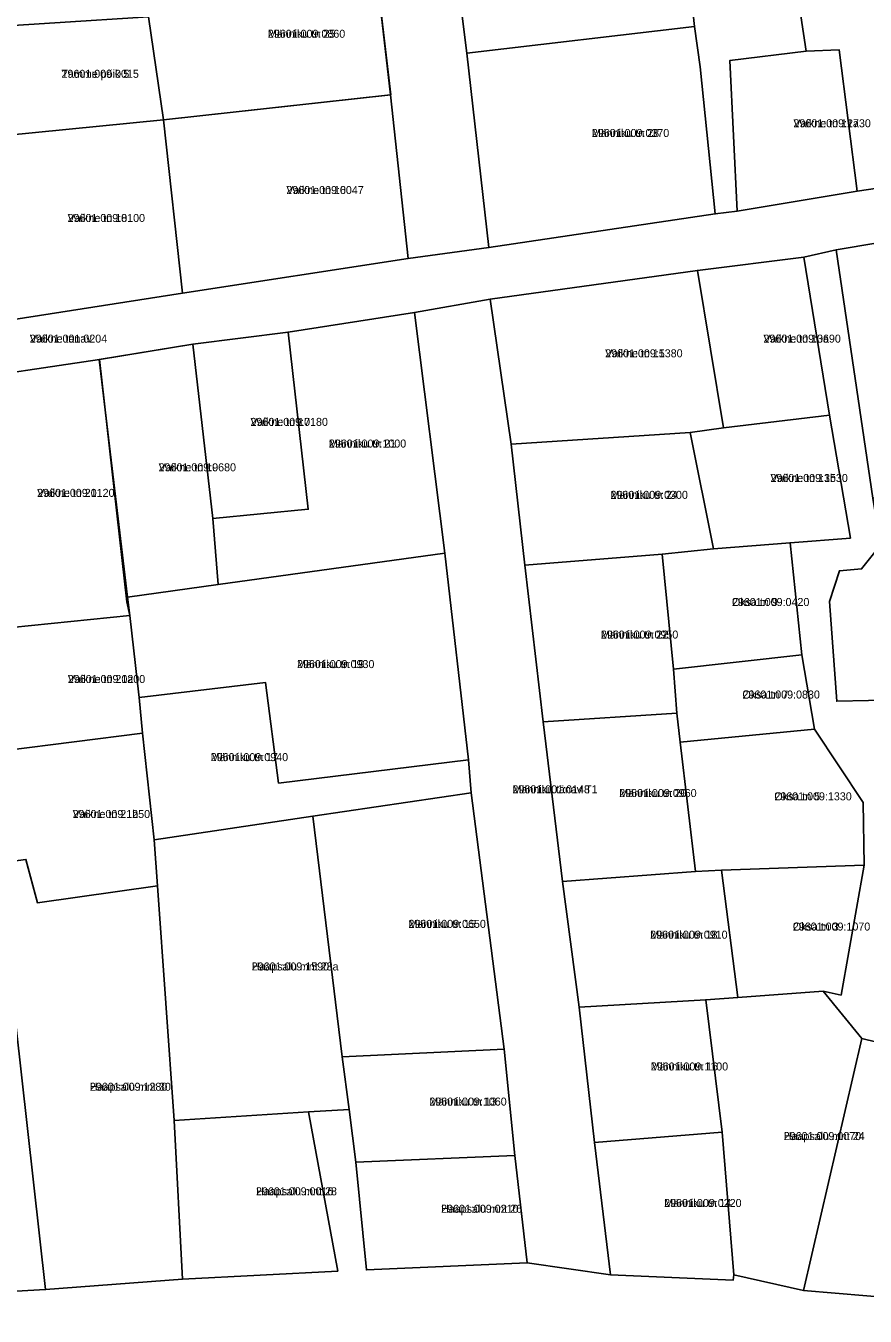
# Model space of a CAD drawing. Extents: x 518839 to 525192, y 6573164 to 6576561.
# Drawn here: x 523208.1 to 523365.3, y 6574453 to 6574694.8 of the extents above; entities that cross this region are included whole.
import ezdxf

# ---------------------------------------------------------------- set-up
doc = ezdxf.new("R2010")
doc.units = 0
for name, color, linetype in [('L_AADRESS', 7, 'Continuous'), ('PIIR', 7, 'Continuous'), ('TUNNUS', 7, 'Continuous')]:
    doc.layers.add(name, color=color, linetype=linetype)

msp = doc.modelspace()

# ---------------------------------------------------------------- linework, layer by layer
at = {"layer": 'PIIR'}
for points in [[(523270.92, 6574729.71), (523267.53, 6574756.92), (523282.17, 6574758.8), (523284.18, 6574742.92), (523288.32, 6574708.6), (523290.68, 6574689.65), (523294.84, 6574653.21), (523279.72, 6574651.19), (523276.41, 6574681.83), (523273.42, 6574707.86)], [(523371.76, 6574716.56), (523372.55, 6574716.47), (523377.4, 6574692.22), (523381.14, 6574666.32), (523363.81, 6574663.75), (523360.45, 6574690.27), (523354.26, 6574689.99), (523350.61, 6574714.52)], [(523341.33, 6574660.04), (523337.24, 6574659.51), (523334.44, 6574687.09), (523333.39, 6574694.64), (523331.45, 6574712.67), (523350.61, 6574714.52), (523354.26, 6574689.99), (523339.99, 6574688.28)], [(523288.32, 6574708.6), (523331.45, 6574712.67), (523333.39, 6574694.64), (523290.68, 6574689.65)], [(523231.04, 6574696.45), (523230.21, 6574703.79), (523273.42, 6574707.86), (523276.47, 6574681.84), (523233.85, 6574677.17)], [(523231.04, 6574696.45), (523233.85, 6574677.17), (523197.86, 6574673.59), (523195.92, 6574694.21)], [(523290.68, 6574689.65), (523333.39, 6574694.64), (523334.44, 6574687.09), (523337.24, 6574659.51), (523294.84, 6574653.21)], [(523339.99, 6574688.28), (523354.26, 6574689.99), (523360.45, 6574690.27), (523363.81, 6574663.75), (523341.33, 6574660.04)], [(523233.85, 6574677.17), (523276.41, 6574681.83), (523279.72, 6574651.19), (523237.4, 6574644.64)], [(523237.4, 6574644.64), (523199.77, 6574638.82), (523196.52, 6574654.74), (523194.48, 6574664.75), (523192.78, 6574673.06), (523197.86, 6574673.59), (523233.85, 6574677.17)], [(523384.07, 6574656.83), (523391.71, 6574615.04), (523392.97, 6574610.47), (523366.8, 6574606.26), (523359.93, 6574652.76)], [(523358.63, 6574621.78), (523338.77, 6574619.44), (523333.92, 6574648.94), (523353.84, 6574651.4)], [(523295.09, 6574643.54), (523333.92, 6574648.94), (523338.77, 6574619.44), (523332.54, 6574618.56), (523299.02, 6574616.36)], [(523286.59, 6574595.96), (523280.89, 6574641.02), (523295.09, 6574643.54), (523299.02, 6574616.36), (523301.6, 6574593.7), (523304.99, 6574564.37), (523308.6, 6574534.46), (523311.75, 6574510.89), (523314.62, 6574485.52), (523317.63, 6574460.76), (523301.99, 6574462.99), (523299.72, 6574483.07), (523297.72, 6574503.04), (523291.5, 6574551.06), (523291.03, 6574557.25)], [(523243.09, 6574602.43), (523260.98, 6574604.17), (523257.22, 6574637.37), (523280.89, 6574641.02), (523286.59, 6574595.96), (523244.08, 6574590.06)], [(523239.37, 6574635.11), (523257.22, 6574637.37), (523260.98, 6574604.17), (523243.09, 6574602.43)], [(523221.81, 6574632.22), (523239.37, 6574635.11), (523243.09, 6574602.43), (523244.08, 6574590.06), (523227.1, 6574587.71)], [(523192.82, 6574624.06), (523193.28, 6574628), (523221.88, 6574632.21), (523227, 6574586.83), (523227.56, 6574584.27), (523201.72, 6574581.64), (523197.9, 6574581.44)], [(523332.54, 6574618.56), (523338.77, 6574619.44), (523358.63, 6574621.78), (523362.58, 6574598.77), (523351.26, 6574597.9), (523336.94, 6574596.79)], [(523299.02, 6574616.36), (523332.54, 6574618.56), (523336.94, 6574596.79), (523327.31, 6574595.75), (523301.6, 6574593.7)], [(523366.8, 6574606.26), (523392.97, 6574610.47), (523387.38, 6574595.16), (523377.83, 6574568.61), (523360.01, 6574568.22), (523358.68, 6574586.91), (523360.51, 6574592.67), (523364.67, 6574593.01), (523367.38, 6574596.44), (523367.82, 6574599.7)], [(523327.31, 6574595.75), (523336.94, 6574596.79), (523351.26, 6574597.9), (523353.46, 6574576.93), (523329.42, 6574574.21)], [(523227.56, 6574584.27), (523227.1, 6574587.71), (523244.08, 6574590.06), (523286.59, 6574595.96), (523291.03, 6574557.25), (523255.43, 6574552.87), (523252.98, 6574571.72), (523229.31, 6574568.94), (523229.02, 6574571.57)], [(523301.6, 6574593.7), (523327.31, 6574595.75), (523329.42, 6574574.21), (523330.05, 6574565.98), (523304.99, 6574564.37)], [(523204.3, 6574558.98), (523201.72, 6574581.64), (523227.56, 6574584.27), (523229.02, 6574571.57), (523229.31, 6574568.94), (523229.96, 6574562.22)], [(523330.05, 6574565.98), (523329.42, 6574574.21), (523353.46, 6574576.93), (523355.85, 6574562.99), (523330.69, 6574560.51)], [(523229.96, 6574562.22), (523229.31, 6574568.94), (523252.98, 6574571.72), (523255.43, 6574552.87), (523291.03, 6574557.25), (523291.5, 6574551.06), (523261.83, 6574546.66), (523232.12, 6574542.26)], [(523304.99, 6574564.37), (523330.05, 6574565.98), (523330.69, 6574560.51), (523333.52, 6574536.29), (523308.6, 6574534.46)], [(523333.52, 6574536.29), (523330.69, 6574560.51), (523355.85, 6574562.99), (523364.95, 6574549.24), (523365.18, 6574537.5), (523338.41, 6574536.55)], [(523208.1, 6574538.57), (523202.76, 6574537.84), (523201.05, 6574557.37), (523200.89, 6574558.52), (523204.3, 6574558.98), (523229.96, 6574562.22), (523232.12, 6574542.26), (523232.73, 6574533.64), (523210.24, 6574530.44)], [(523261.83, 6574546.66), (523291.5, 6574551.06), (523297.72, 6574503.04), (523267.33, 6574501.58)], [(523261.83, 6574546.66), (523267.33, 6574501.58), (523268.66, 6574491.72), (523261.01, 6574491.27), (523235.87, 6574489.63), (523232.73, 6574533.64), (523232.12, 6574542.26)], [(523172.73, 6574532.99), (523202.76, 6574537.84), (523211.77, 6574457.97), (523182.12, 6574456.3)], [(523202.76, 6574537.84), (523208.1, 6574538.57), (523210.24, 6574530.44), (523232.73, 6574533.64), (523235.87, 6574489.63), (523237.41, 6574459.95), (523211.77, 6574457.97)], [(523308.6, 6574534.46), (523333.52, 6574536.29), (523338.41, 6574536.55), (523341.51, 6574512.72), (523335.47, 6574512.29), (523311.75, 6574510.89)], [(523338.41, 6574536.55), (523365.18, 6574537.5), (523360.84, 6574513.15), (523357.47, 6574513.86), (523341.51, 6574512.72)], [(523311.75, 6574510.89), (523335.47, 6574512.29), (523338.56, 6574487.48), (523314.62, 6574485.52)], [(523338.56, 6574487.48), (523335.47, 6574512.29), (523341.51, 6574512.72), (523357.47, 6574513.86), (523364.71, 6574505), (523353.78, 6574457.82), (523340.75, 6574460.73)], [(523353.78, 6574457.82), (523364.71, 6574505), (523388.29, 6574499.29), (523377.5, 6574455.78)], [(523267.33, 6574501.58), (523297.72, 6574503.04), (523299.72, 6574483.07), (523269.88, 6574481.86), (523268.66, 6574491.72)], [(523261.01, 6574491.27), (523266.52, 6574461.43), (523237.41, 6574459.95), (523235.87, 6574489.63)], [(523314.62, 6574485.52), (523338.56, 6574487.48), (523340.75, 6574460.73), (523340.58, 6574459.73), (523317.63, 6574460.76)], [(523269.88, 6574481.86), (523299.72, 6574483.07), (523301.99, 6574462.99), (523271.9, 6574461.67)]]:
    msp.add_lwpolyline(points, close=True, dxfattribs=at)
for points in [[(522971.01, 6574608.2), (523016.84, 6574613.87), (523036.69, 6574614.32), (523053.73, 6574617.31), (523078.72, 6574621.41), (523103.27, 6574625.01), (523133.09, 6574629.32), (523162.42, 6574633.47), (523199.77, 6574638.82), (523237.4, 6574644.64), (523279.72, 6574651.19), (523294.84, 6574653.21), (523337.24, 6574659.51), (523341.33, 6574660.04), (523363.81, 6574663.75), (523381.14, 6574666.32)], [(523384.07, 6574656.83), (523359.93, 6574652.76), (523353.84, 6574651.4), (523333.92, 6574648.94), (523295.09, 6574643.54), (523280.89, 6574641.02), (523257.22, 6574637.37), (523239.37, 6574635.11), (523221.88, 6574632.21), (523193.28, 6574628)], [(523388.29, 6574499.29), (523364.71, 6574505), (523357.47, 6574513.86), (523360.84, 6574513.15), (523365.18, 6574537.5), (523364.95, 6574549.24), (523355.85, 6574562.99), (523353.46, 6574576.93), (523351.26, 6574597.9), (523362.58, 6574598.77), (523358.63, 6574621.78), (523353.84, 6574651.4), (523359.93, 6574652.76), (523366.8, 6574606.26)], [(523367.38, 6574596.44), (523364.67, 6574593.01), (523360.51, 6574592.67), (523358.68, 6574586.91), (523360.01, 6574568.22), (523377.83, 6574568.61)], [(522984.54, 6574464.85), (523007.82, 6574461.09), (523032.83, 6574456.91), (523042.53, 6574455.82), (523091.93, 6574452.99), (523122.12, 6574453.34), (523152.21, 6574454.88), (523156.2, 6574455.07), (523182.12, 6574456.3), (523211.77, 6574457.97), (523237.41, 6574459.95), (523266.52, 6574461.43), (523261.01, 6574491.27), (523268.66, 6574491.72), (523269.88, 6574481.86), (523271.9, 6574461.67), (523301.99, 6574462.99), (523317.63, 6574460.76), (523340.58, 6574459.73), (523340.75, 6574460.73), (523353.78, 6574457.82), (523377.5, 6574455.78)]]:
    msp.add_lwpolyline(points, dxfattribs=at)

# ---------------------------------------------------------------- texts
at = {"layer": 'L_AADRESS'}
for s, p in [('Männiku tn 25', (523253.42, 6574692.52)), ('Tamme põik 5', (523214.75, 6574685.02)), ('Vaikne tn 12a', (523351.9, 6574675.75)), ('Männiku tn 28', (523314.13, 6574673.93)), ('Vaikne tn 16', (523256.89, 6574663.24)), ('Vaikne tn 18', (523215.9, 6574658)), ('Vaikne tänav', (523208.81, 6574635.4)), ('Vaikne tn 13a', (523346.28, 6574635.4)), ('Vaikne tn 15', (523316.63, 6574632.65)), ('Vaikne tn 17', (523250.17, 6574619.8)), ('Männiku tn 21', (523264.84, 6574615.74)), ('Vaikne tn 19', (523232.95, 6574611.29)), ('Vaikne tn 13b', (523347.59, 6574609.29)), ('Vaikne tn 21', (523210.19, 6574606.5)), ('Männiku tn 24', (523317.62, 6574606.13)), ('Oksa tn 9', (523340.38, 6574586.05)), ('Männiku tn 22', (523315.82, 6574579.95)), ('Männiku tn 19', (523258.88, 6574574.42)), ('Vaikne tn 21a', (523215.94, 6574571.62)), ('Oksa tn 7', (523342.35, 6574568.72)), ('Männiku tn 17', (523242.71, 6574556.99)), ('Männiku tänav T1', (523299.26, 6574550.96)), ('Männiku tn 20', (523319.26, 6574550.26)), ('Oksa tn 5', (523348.32, 6574549.64)), ('Vaikne tn 21b', (523216.85, 6574546.33)), ('Männiku tn 15', (523279.77, 6574525.75)), ('Oksa tn 3', (523351.79, 6574525.24)), ('Männiku tn 18', (523325.06, 6574523.72)), ('Haapsalu mnt 28a', (523250.39, 6574517.77)), ('Männiku tn 16', (523325.16, 6574499.03)), ('Haapsalu mnt 30', (523220.08, 6574495.23)), ('Männiku tn 13', (523283.67, 6574492.45)), ('Haapsalu mnt 24', (523350.09, 6574485.99)), ('Haapsalu mnt 28', (523251.2, 6574475.64)), ('Haapsalu mnt 26', (523285.88, 6574472.37)), ('Männiku tn 14', (523327.68, 6574473.45))]:
    msp.add_text(s, height=1.5, dxfattribs=at).set_placement(p)
at = {"layer": 'TUNNUS'}
for s, p in [('29601:009:0860', (523253.42, 6574692.52)), ('29601:009:0015', (523214.75, 6574685.02)), ('29601:009:1730', (523351.9, 6574675.75)), ('29601:009:0370', (523314.13, 6574673.93)), ('29601:009:0047', (523256.89, 6574663.24)), ('29601:009:0100', (523215.9, 6574658)), ('29601:001:0204', (523208.81, 6574635.4)), ('29601:009:0690', (523346.28, 6574635.4)), ('29601:009:1380', (523316.63, 6574632.65)), ('29601:009:0180', (523250.17, 6574619.8)), ('29601:009:1000', (523264.84, 6574615.74)), ('29601:009:0680', (523232.95, 6574611.29)), ('29601:009:1530', (523347.59, 6574609.29)), ('29601:009:0120', (523210.19, 6574606.5)), ('29601:009:0300', (523317.62, 6574606.13)), ('29601:009:0420', (523340.38, 6574586.05)), ('29601:009:0950', (523315.82, 6574579.95)), ('29601:009:0930', (523258.88, 6574574.42)), ('29601:009:0200', (523215.94, 6574571.62)), ('29601:009:0830', (523342.35, 6574568.72)), ('29601:009:0940', (523242.71, 6574556.99)), ('29601:001:0148', (523299.26, 6574550.96)), ('29601:009:0960', (523319.26, 6574550.26)), ('29601:009:1330', (523348.32, 6574549.64)), ('29601:009:1250', (523216.85, 6574546.33)), ('29601:009:0650', (523279.77, 6574525.75)), ('29601:009:1070', (523351.79, 6574525.24)), ('29601:009:0910', (523325.06, 6574523.72)), ('29601:009:1590', (523250.39, 6574517.77)), ('29601:009:1100', (523325.16, 6574499.03)), ('29601:009:1280', (523220.08, 6574495.23)), ('29601:009:1060', (523283.67, 6574492.45)), ('29601:009:0070', (523350.09, 6574485.99)), ('29601:009:0016', (523251.2, 6574475.64)), ('29601:009:0210', (523285.88, 6574472.37)), ('29601:009:0220', (523327.68, 6574473.45))]:
    msp.add_text(s, height=1.5, dxfattribs=at).set_placement(p)

doc.saveas('drawing.dxf')
